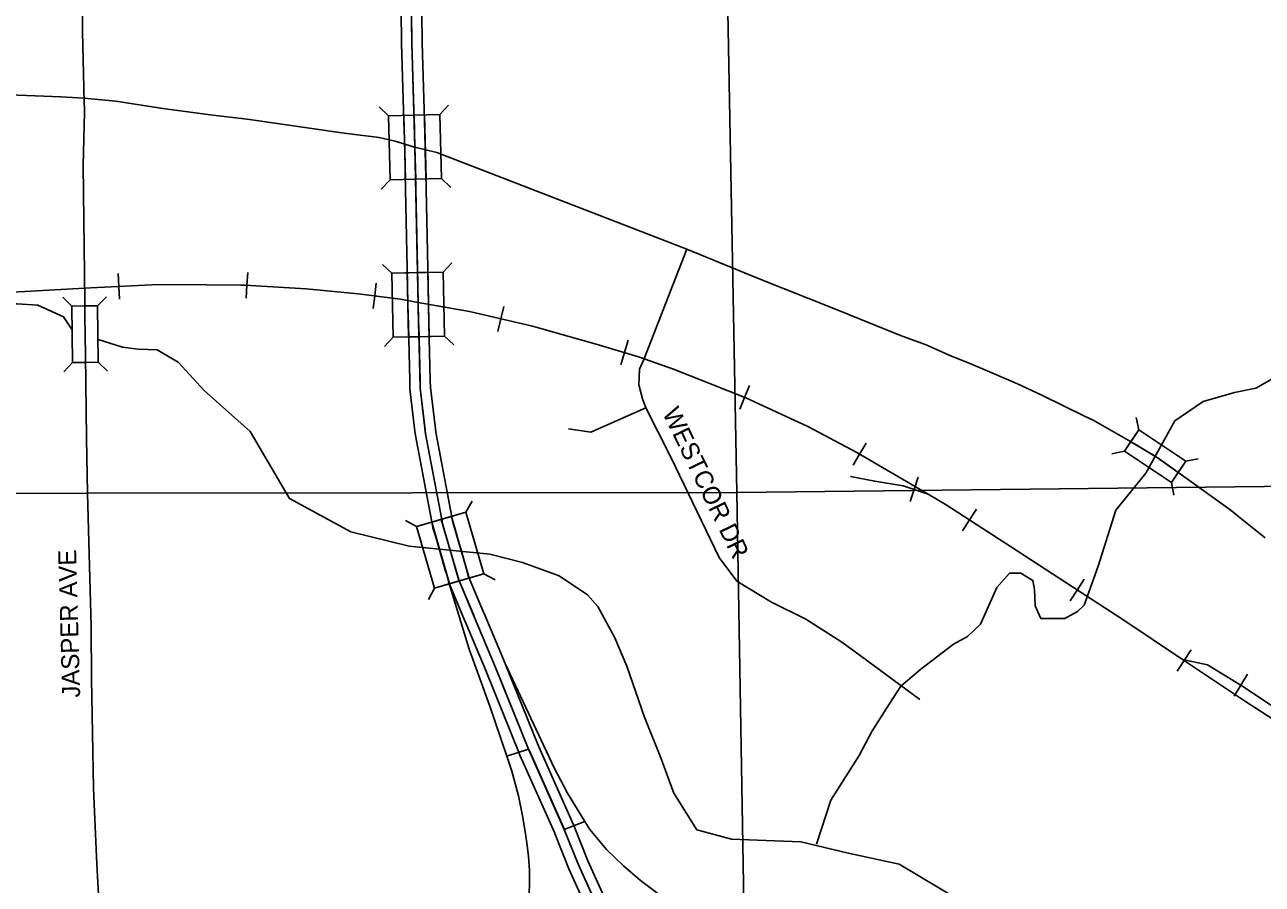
# Model space of a CAD drawing. Extents: x 281.94 to 289.14, y 116.09 to 120.89.
# Drawn here: x 285.132 to 286.097, y 118.127 to 118.797 of the extents above; entities that cross this region are included whole.
import ezdxf

# ---------------------------------------------------------------- set-up
doc = ezdxf.new("R2010")
doc.units = 0
for name, color, linetype in [('tdCiAdjCityStreetCL', 7, 'Continuous'), ('tdCiCityStreetCL', 7, 'Continuous'), ('tdCiCityStreetTxt', 7, 'Continuous'), ('tdCiCorpBndry', 7, 'Continuous'), ('tdCiCorpBndryPart', 7, 'Continuous'), ('tdCiHydroRiver', 7, 'Continuous'), ('tdCiInt', 7, 'Continuous'), ('tdCiIntCL', 7, 'Continuous'), ('tdCiIntRamp', 7, 'Continuous'), ('tdCiIntRampCL', 7, 'Continuous'), ('tdCiPriCL', 7, 'Continuous'), ('tdCiPriDiv', 7, 'Continuous'), ('tdCiRRCL', 7, 'Continuous'), ('tdCiSecText', 7, 'Continuous'), ('tdCiSectLine', 7, 'Continuous'), ('tdCiStrucDataInt', 7, 'Continuous'), ('tdCiStrucDataMuni', 7, 'Continuous'), ('tdCiStrucDataPriNonDiv', 7, 'Continuous')]:
    doc.layers.add(name, color=color, linetype=linetype)

msp = doc.modelspace()

# ---------------------------------------------------------------- linework, layer by layer
at = {"layer": 'tdCiAdjCityStreetCL'}
for points in [[(285.64814, 118.62187), (285.63758, 118.5944), (285.61469, 118.53568), (285.61122, 118.52811), (285.61074, 118.51597), (285.61359, 118.505), (285.6162, 118.49814)], [(285.55595, 118.48169), (285.57336, 118.47915), (285.6162, 118.49814)], [(285.6162, 118.49814), (285.63551, 118.45962), (285.6734, 118.38141), (285.687, 118.36295), (285.71421, 118.34644), (285.74092, 118.33332), (285.76813, 118.31583), (285.77839, 118.3085), (285.82987, 118.27054)]]:
    msp.add_lwpolyline(points, dxfattribs=at)
at = {"layer": 'tdCiCityStreetCL'}
msp.add_lwpolyline([(285.19066, 118.09462), (285.18812, 118.1422), (285.18631, 118.18338), (285.18551, 118.20146), (285.18402, 118.28681), (285.18365, 118.32743), (285.18074, 118.43145), (285.17992, 118.47428), (285.17917, 118.53902), (285.17899, 118.55441), (285.17881, 118.56991), (285.17868, 118.5813), (285.17745, 118.68694), (285.17843, 118.72837), (285.17814, 118.73964), (285.17804, 118.74363), (285.17794, 118.74761), (285.17695, 118.79126), (285.17657, 118.85742)], dxfattribs=at)
at = {"layer": 'tdCiCorpBndry'}
msp.add_lwpolyline([(285.60634, 118.04751), (285.56352, 118.14174), (285.55256, 118.16928), (285.52478, 118.23175), (285.499, 118.29566), (285.48265, 118.33456), (285.47019, 118.36445), (285.45783, 118.40692), (285.44445, 118.47778), (285.44025, 118.51339), (285.43865, 118.57848), (285.43614, 118.70127), (285.43376, 118.78246), (285.43149, 118.93422)], dxfattribs=at)
at = {"layer": 'tdCiCorpBndryPart'}
msp.add_lwpolyline([(285.60634, 118.04751), (285.56352, 118.14174), (285.55256, 118.16928), (285.52478, 118.23175), (285.499, 118.29566), (285.48265, 118.33456), (285.47019, 118.36445), (285.45783, 118.40692), (285.44445, 118.47778), (285.44025, 118.51339), (285.43865, 118.57848), (285.43614, 118.70127), (285.43376, 118.78246), (285.43149, 118.93422)], dxfattribs=at)
at = {"layer": 'tdCiHydroRiver'}
for points in [[(286.00589, 118.44705), (286.02857, 118.48798), (286.05069, 118.50292), (286.07503, 118.51011), (286.09163, 118.51343), (286.1038, 118.52006), (286.11375, 118.53444), (286.11652, 118.55104), (286.11431, 118.56376), (286.11043, 118.64839), (286.11707, 118.67715), (286.13311, 118.7026), (286.14417, 118.73136), (286.15247, 118.75293), (286.16907, 118.76731), (286.19119, 118.77616), (286.20611, 118.78635)], [(285.16894, 118.55896), (285.16216, 118.56913), (285.14205, 118.57813), (285.12564, 118.57919), (285.10394, 118.57919), (285.08754, 118.5776), (285.0759, 118.57019), (285.06161, 118.56119), (285.0542, 118.55008), (285.04573, 118.53473)], [(285.49449, 118.38391), (285.43152, 118.39026), (285.38601, 118.40138), (285.33838, 118.42731), (285.30769, 118.4797), (285.2717, 118.51145), (285.25159, 118.53368), (285.23519, 118.5432), (285.22037, 118.54373), (285.2082, 118.54532), (285.18903, 118.55131)], [(285.95777, 118.34417), (285.96883, 118.37459), (285.98266, 118.41829), (286.00589, 118.44705)], [(285.95379, 117.97561), (285.9512, 117.98754), (285.93267, 118.02776), (285.90145, 118.08491), (285.85806, 118.11561), (285.8136, 118.14207), (285.77285, 118.15106), (285.73687, 118.15953), (285.68289, 118.16165), (285.6559, 118.16906), (285.63791, 118.19763), (285.62785, 118.22515), (285.61515, 118.2569), (285.60139, 118.29659), (285.59187, 118.31882), (285.57864, 118.34316), (285.5707, 118.35216), (285.54847, 118.36698), (285.5199, 118.37756), (285.49449, 118.38391)], [(285.74924, 118.15776), (285.7603, 118.19205), (285.78242, 118.2269), (285.79238, 118.24571), (285.80344, 118.26341), (285.81506, 118.28111), (285.83055, 118.29438), (285.85599, 118.31374), (285.86705, 118.31983), (285.87701, 118.32923), (285.88973, 118.35799), (285.89969, 118.36906), (285.90854, 118.36906), (285.91794, 118.36353), (285.91905, 118.35634), (285.9196, 118.34361), (285.92403, 118.33366), (285.94283, 118.33366), (285.95279, 118.33919), (285.95777, 118.34417)]]:
    msp.add_lwpolyline(points, dxfattribs=at)
at = {"layer": 'tdCiInt'}
for points in [[(285.58582, 118.07334), (285.55616, 118.13861), (285.54518, 118.16617), (285.54507, 118.16643), (285.518, 118.22729), (285.51741, 118.22863), (285.49185, 118.29199), (285.4916, 118.29262), (285.47528, 118.33148), (285.47482, 118.33258), (285.46263, 118.36178), (285.46236, 118.36271), (285.4606, 118.36874), (285.46007, 118.37058), (285.45206, 118.39811), (285.45153, 118.39992), (285.45017, 118.40459), (285.45004, 118.40506), (285.43654, 118.47656), (285.43615, 118.47986), (285.43226, 118.51282), (285.43211, 118.51925), (285.43104, 118.56255), (285.43103, 118.56292), (285.43065, 118.5783), (285.43033, 118.59402), (285.43032, 118.59437), (285.42855, 118.68084), (285.42848, 118.68447), (285.42814, 118.70107), (285.42755, 118.72131), (285.42576, 118.78228), (285.42571, 118.78589), (285.42349, 118.93407)], [(285.60039, 118.07995), (285.57088, 118.14488), (285.55993, 118.17238), (285.55969, 118.17293), (285.53262, 118.23379), (285.53214, 118.23487), (285.50669, 118.29797), (285.50639, 118.29871), (285.49003, 118.33765), (285.48958, 118.33874), (285.47774, 118.36712), (285.47772, 118.36718), (285.47597, 118.37321), (285.47543, 118.37505), (285.46742, 118.40258), (285.46689, 118.4044), (285.46561, 118.40879), (285.45236, 118.47899), (285.45204, 118.48173), (285.44824, 118.51396), (285.4481, 118.51965), (285.44703, 118.56295), (285.44702, 118.56332), (285.44664, 118.57866), (285.44632, 118.59434), (285.44632, 118.5947), (285.44455, 118.68117), (285.44447, 118.6848), (285.44413, 118.70147), (285.44354, 118.72178), (285.44176, 118.78264), (285.44171, 118.78613), (285.43949, 118.93436)]]:
    msp.add_lwpolyline(points, dxfattribs=at)
at = {"layer": 'tdCiIntCL'}
msp.add_lwpolyline([(285.5931, 118.07665), (285.56352, 118.14174), (285.55256, 118.16928), (285.55238, 118.16968), (285.52531, 118.23054), (285.52478, 118.23175), (285.49927, 118.29498), (285.499, 118.29566), (285.48265, 118.33456), (285.4822, 118.33566), (285.47019, 118.36445), (285.47004, 118.36494), (285.46829, 118.37098), (285.46775, 118.37281), (285.45974, 118.40034), (285.45921, 118.40216), (285.45786, 118.40682), (285.45783, 118.40692), (285.44445, 118.47778), (285.4441, 118.48079), (285.44025, 118.51339), (285.4401, 118.51945), (285.43903, 118.56275), (285.43902, 118.56312), (285.43865, 118.57848), (285.43832, 118.59418), (285.43832, 118.59453), (285.43655, 118.68101), (285.43648, 118.68464), (285.43614, 118.70127), (285.43554, 118.72155), (285.43376, 118.78246), (285.43371, 118.78601), (285.43149, 118.93422)], dxfattribs=at)
at = {"layer": 'tdCiIntRamp'}
for points in [[(285.46263, 118.36178), (285.47847, 118.30998), (285.49463, 118.26541), (285.50776, 118.22637), (285.51175, 118.21473), (285.5168, 118.1956), (285.51999, 118.17993), (285.52185, 118.1693), (285.52346, 118.15876), (285.52462, 118.14816), (285.52532, 118.13751), (285.52532, 118.12674), (285.52454, 118.10412)], [(285.85313, 117.98793), (285.85057, 117.98873), (285.84534, 117.99036), (285.82461, 117.99895), (285.79791, 118.01063), (285.77478, 118.02302), (285.74713, 118.04019), (285.71948, 118.0583), (285.68229, 118.08238), (285.64772, 118.10479), (285.62555, 118.11933), (285.61196, 118.12958), (285.59885, 118.14079), (285.5855, 118.15366), (285.57239, 118.16915), (285.56846, 118.17535), (285.55504, 118.1975), (285.54459, 118.21725), (285.50639, 118.29871)]]:
    msp.add_lwpolyline(points, dxfattribs=at)
at = {"layer": 'tdCiIntRampCL'}
for points in [[(285.52478, 118.23175), (285.50776, 118.22637), (285.51175, 118.21473), (285.5168, 118.1956), (285.51999, 118.17993), (285.52185, 118.1693), (285.52346, 118.15876), (285.52462, 118.14816), (285.52532, 118.13751), (285.52532, 118.12674), (285.52454, 118.10412)], [(285.62555, 118.11933), (285.61196, 118.12958), (285.59885, 118.14079), (285.5855, 118.15366), (285.57239, 118.16915), (285.56846, 118.17535), (285.55256, 118.16928)]]:
    msp.add_lwpolyline(points, dxfattribs=at)
at = {"layer": 'tdCiPriCL'}
msp.add_lwpolyline([(285.11318, 118.74249), (285.15993, 118.7407), (285.17814, 118.73964), (285.20295, 118.73713), (285.23948, 118.73161), (285.2786, 118.72625), (285.30538, 118.72304), (285.38088, 118.71213), (285.40821, 118.70879), (285.42065, 118.70596), (285.43589, 118.70135), (285.43614, 118.70127), (285.45326, 118.69713), (285.64814, 118.62187), (285.70328, 118.59914), (285.7627, 118.5756), (285.81481, 118.55434), (285.83478, 118.5472), (285.85263, 118.53924), (285.87015, 118.53203), (285.88054, 118.52768), (285.90588, 118.51684), (285.92552, 118.50775), (285.95768, 118.49193), (285.96481, 118.48843), (285.9976, 118.4696), (286.01297, 118.4604), (286.01468, 118.45938), (286.01578, 118.45872), (286.01635, 118.45831), (286.04289, 118.4394), (286.07244, 118.41797), (286.07861, 118.41308), (286.09903, 118.39661)], dxfattribs=at)
at = {"layer": 'tdCiPriDiv'}
msp.add_lwpolyline([(285.11318, 118.74249), (285.15993, 118.7407), (285.17814, 118.73964), (285.20295, 118.73713), (285.23948, 118.73161), (285.2786, 118.72625), (285.30538, 118.72304), (285.38088, 118.71213), (285.40821, 118.70879), (285.42065, 118.70596), (285.43589, 118.70135), (285.43614, 118.70127), (285.45326, 118.69713), (285.64814, 118.62187), (285.70328, 118.59914), (285.7627, 118.5756), (285.81481, 118.55434), (285.83478, 118.5472), (285.85263, 118.53924), (285.87015, 118.53203), (285.88054, 118.52768), (285.90588, 118.51684), (285.92552, 118.50775), (285.95768, 118.49193), (285.96481, 118.48843), (285.9976, 118.4696), (286.01297, 118.4604), (286.01468, 118.45938), (286.01578, 118.45872), (286.01635, 118.45831), (286.04289, 118.4394), (286.07244, 118.41797), (286.07861, 118.41308), (286.09903, 118.39661)], dxfattribs=at)
at = {"layer": 'tdCiRRCL'}
for points in [[(285.20569, 118.58276), (285.20517, 118.59275), (285.20466, 118.60274)], [(285.30451, 118.58368), (285.30513, 118.59366), (285.30574, 118.60365)], [(285.06316, 118.58517), (285.13197, 118.58888), (285.18338, 118.59162), (285.23616, 118.59435), (285.2735, 118.59396), (285.30027, 118.59379), (285.30341, 118.59377), (285.3513, 118.59084), (285.39177, 118.58693), (285.4248, 118.58282), (285.43861, 118.58008), (285.47876, 118.57305), (285.52782, 118.56171), (285.53505, 118.55969), (285.57747, 118.54783), (285.61031, 118.53786), (285.63768, 118.52828), (285.69418, 118.5058), (285.74246, 118.48352), (285.78077, 118.46319), (285.83626, 118.43077), (285.85037, 118.42253), (285.90041, 118.38988), (285.94947, 118.35782), (285.98877, 118.33241), (286.03457, 118.30181), (286.08357, 118.26907), (286.13792, 118.23389)], [(285.06316, 118.58517), (285.13197, 118.58888), (285.18338, 118.59162), (285.23616, 118.59435), (285.2735, 118.59396), (285.30027, 118.59379), (285.30341, 118.59377), (285.3513, 118.59084), (285.39177, 118.58693), (285.4248, 118.58282), (285.43861, 118.58008), (285.47876, 118.57305), (285.52782, 118.56171), (285.53505, 118.55969), (285.57747, 118.54783), (285.61031, 118.53786), (285.63768, 118.52828), (285.69418, 118.5058), (285.74246, 118.48352), (285.78077, 118.46319), (285.83626, 118.43077), (285.85037, 118.42253), (285.90041, 118.38988), (285.94947, 118.35782), (285.98877, 118.33241), (286.03457, 118.30181), (286.08357, 118.26907), (286.13792, 118.23389)], [(285.40352, 118.57539), (285.40475, 118.58531), (285.40598, 118.59524)], [(285.50082, 118.55768), (285.50308, 118.56743), (285.50533, 118.57717)], [(285.59662, 118.53156), (285.59953, 118.54114), (285.60243, 118.55071)], [(285.68948, 118.4969), (285.69318, 118.5062), (285.69688, 118.51549)], [(285.77778, 118.45335), (285.78282, 118.46199), (285.78787, 118.47063)], [(285.77567, 118.4446), (285.79459, 118.44074), (285.8169, 118.43732), (285.83626, 118.43077)], [(285.77567, 118.4446), (285.79459, 118.44074), (285.8169, 118.43732), (285.83626, 118.43077)], [(285.82213, 118.42499), (285.82534, 118.43446), (285.82855, 118.44394)], [(285.86314, 118.40225), (285.8686, 118.41063), (285.87407, 118.41901)], [(285.94691, 118.34757), (285.95234, 118.35597), (285.95777, 118.36437)], [(286.03029, 118.29264), (286.03585, 118.30096), (286.0414, 118.30927)], [(286.28418, 118.13769), (286.26818, 118.15657), (286.23728, 118.17881), (286.19889, 118.2029), (286.17132, 118.22128), (286.15044, 118.23435), (286.12547, 118.25152), (286.0808, 118.2813), (286.05414, 118.29769), (286.03457, 118.30181)], [(286.28418, 118.13769), (286.26818, 118.15657), (286.23728, 118.17881), (286.19889, 118.2029), (286.17132, 118.22128), (286.15044, 118.23435), (286.12547, 118.25152), (286.0808, 118.2813), (286.05414, 118.29769), (286.03457, 118.30181)], [(286.08528, 118.29029), (286.08004, 118.28177), (286.0748, 118.27325)]]:
    msp.add_lwpolyline(points, dxfattribs=at)
at = {"layer": 'tdCiSectLine'}
for points in [[(285.67077, 119.30689), (285.68714, 118.43194), (285.70175, 117.57749)], [(284.97643, 118.43137), (285.18074, 118.43145), (285.68714, 118.43194), (286.41843, 118.44026)]]:
    msp.add_lwpolyline(points, dxfattribs=at)
at = {"layer": 'tdCiStrucDataInt'}
for p, q in [((285.42752, 118.72607), (285.42876, 118.67608)), ((285.44351, 118.72646), (285.44475, 118.67648)), ((285.43008, 118.60332), (285.43121, 118.55333)), ((285.44608, 118.60368), (285.44721, 118.55369)), ((285.44931, 118.4089), (285.46303, 118.36082)), ((285.46475, 118.41339), (285.47849, 118.36532))]:
    msp.add_line(p, q, dxfattribs=at)
for points in [[(285.45551, 118.72676), (285.43551, 118.72627), (285.41552, 118.72577), (285.40828, 118.73266)], [(285.45675, 118.67678), (285.45551, 118.72676), (285.4624, 118.73401)], [(285.41552, 118.72577), (285.41676, 118.67578), (285.40987, 118.66854)], [(285.43551, 118.72627), (285.43614, 118.70127), (285.43676, 118.67628)], [(285.41676, 118.67578), (285.43676, 118.67628), (285.45675, 118.67678), (285.464, 118.66988)], [(285.45808, 118.60395), (285.43808, 118.6035), (285.41809, 118.60305), (285.41086, 118.60996)], [(285.4592, 118.55397), (285.45808, 118.60395), (285.46499, 118.61118)], [(285.41809, 118.60305), (285.41921, 118.55306), (285.4123, 118.54584)], [(285.43808, 118.6035), (285.43864, 118.57851), (285.43921, 118.55351)], [(285.41921, 118.55306), (285.43921, 118.55351), (285.4592, 118.55397), (285.46643, 118.54706)], [(285.4898, 118.36861), (285.47583, 118.41662), (285.48065, 118.42538)], [(285.47583, 118.41662), (285.45663, 118.41103), (285.43743, 118.40544), (285.42866, 118.41026)], [(285.43743, 118.40544), (285.4514, 118.35743), (285.44658, 118.34867)], [(285.45663, 118.41103), (285.46362, 118.38703), (285.4706, 118.36302)], [(285.4514, 118.35743), (285.4706, 118.36302), (285.4898, 118.36861), (285.49857, 118.3638)]]:
    msp.add_lwpolyline(points, dxfattribs=at)
for points in [[(285.45551, 118.72676), (285.45675, 118.67678), (285.41676, 118.67578), (285.41552, 118.72577)], [(285.45808, 118.60395), (285.4592, 118.55397), (285.41921, 118.55306), (285.41809, 118.60305)], [(285.47583, 118.41662), (285.4898, 118.36861), (285.4514, 118.35743), (285.43743, 118.40544)]]:
    msp.add_lwpolyline(points, close=True, dxfattribs=at)
at = {"layer": 'tdCiStrucDataMuni'}
for points in [[(285.18872, 118.57758), (285.17872, 118.57747), (285.16872, 118.57735), (285.16157, 118.58434)], [(285.18923, 118.53359), (285.18872, 118.57758), (285.19571, 118.58474)], [(285.16872, 118.57735), (285.16923, 118.53335), (285.16225, 118.5262)], [(285.16923, 118.53335), (285.17923, 118.53347), (285.18923, 118.53359), (285.19639, 118.5266)]]:
    msp.add_lwpolyline(points, dxfattribs=at)
at = {"layer": 'tdCiStrucDataPriNonDiv'}
for points in [[(286.03706, 118.45638), (286.00045, 118.48078), (285.99849, 118.49059)], [(286.00045, 118.48078), (285.9949, 118.47246), (285.98936, 118.46414), (285.97955, 118.46218)], [(285.98936, 118.46414), (286.02597, 118.43974), (286.02793, 118.42993)], [(285.99427, 118.47151), (286.01321, 118.46026), (286.03127, 118.44769)], [(286.02597, 118.43974), (286.03152, 118.44806), (286.03706, 118.45638), (286.04687, 118.45834)]]:
    msp.add_lwpolyline(points, dxfattribs=at)
msp.add_lwpolyline([(286.00045, 118.48078), (286.03706, 118.45638), (286.02597, 118.43974), (285.98936, 118.46414)], close=True, dxfattribs=at)

# ---------------------------------------------------------------- texts
at = {"layer": 'tdCiCityStreetTxt'}
msp.add_text('JASPER AVE', height=0.014, rotation=91.59979, dxfattribs=at).set_placement((285.17514, 118.27222))
at = {"layer": 'tdCiSecText'}
msp.add_text('WESTCOR DR', height=0.014, rotation=295.8489, dxfattribs=at).set_placement((285.62877, 118.49417))

doc.saveas('drawing.dxf')
